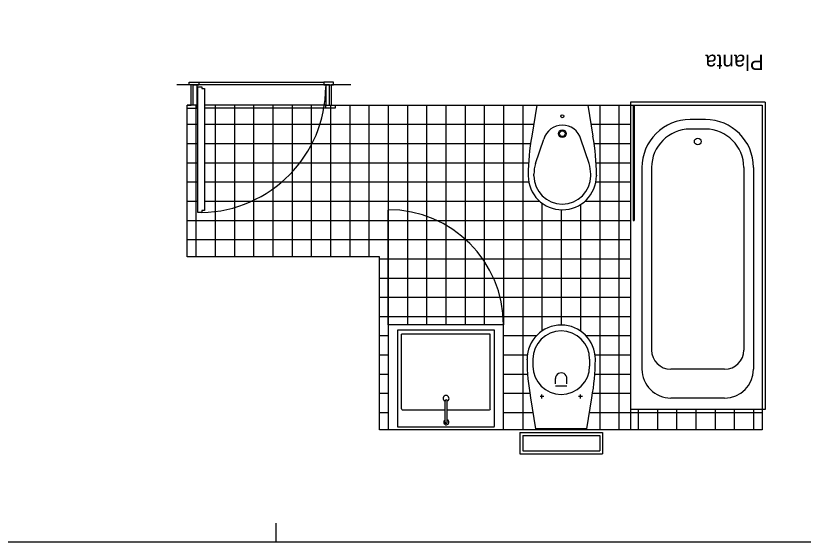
# Model space of a CAD drawing. Extents: x 1302 to 1313.6, y -284.7 to -278.8.
# Drawn here: x 1304.384 to 1308.48, y -284.712 to -281.971 of the extents above; entities that cross this region are included whole.
import ezdxf

# ---------------------------------------------------------------- set-up
doc = ezdxf.new("R2010")
doc.units = 0
for name, color, linetype in [('Level 1', 7, 'Continuous'), ('Level 10', 7, 'Continuous'), ('Level 11', 7, 'Continuous'), ('Level 13', 7, 'Continuous'), ('Level 2', 7, 'Continuous'), ('Level 36', 7, 'Continuous'), ('Level 4', 7, 'Continuous'), ('Level 60', 7, 'Continuous'), ('Level 62', 7, 'Continuous')]:
    doc.layers.add(name, color=color, linetype=linetype)

msp = doc.modelspace()

# ---------------------------------------------------------------- linework, layer by layer
at = {"layer": 'Level 1'}
for p, q in [((1305.2959, -282.3311), (1305.2209, -282.3311)), ((1305.2959, -282.4361), (1305.2959, -282.3311)), ((1306.1259, -282.3311), (1306.0259, -282.3311)), ((1306.0259, -282.4361), (1306.0259, -282.3311)), ((1305.2759, -283.2261), (1305.2759, -282.4361)), ((1305.2759, -282.4361), (1305.2959, -282.4361)), ((1306.0259, -282.4361), (1308.2659, -282.4361)), ((1308.2659, -282.4361), (1308.2659, -284.1261)), ((1306.2759, -283.2261), (1305.2759, -283.2261)), ((1306.2759, -284.1261), (1306.2759, -283.2261)), ((1308.2659, -284.1261), (1306.2759, -284.1261))]:
    msp.add_line(p, q, dxfattribs=at)
at = {"layer": 'Level 10'}
for p, q in [((1305.9859, -282.3311), (1305.3359, -282.3311)), ((1305.3209, -282.4361), (1305.3209, -283.2261)), ((1305.9959, -282.4361), (1305.3659, -282.4361)), ((1305.4209, -282.4361), (1305.4209, -283.2261)), ((1305.5209, -282.4361), (1305.5209, -283.2261)), ((1305.6209, -282.4361), (1305.6209, -283.2261)), ((1305.7209, -282.4361), (1305.7209, -283.2261)), ((1305.8209, -282.4361), (1305.8209, -283.2261)), ((1305.9209, -282.4361), (1305.9209, -283.2261)), ((1306.0209, -282.4361), (1306.0209, -283.2261)), ((1306.1209, -282.4361), (1306.1209, -283.2261)), ((1306.2209, -282.4361), (1306.2209, -283.2261)), ((1306.3209, -282.4361), (1306.3209, -283.5806)), ((1306.4209, -282.4361), (1306.4209, -283.5806)), ((1306.5209, -282.4361), (1306.5209, -283.5806)), ((1306.6209, -282.4361), (1306.6209, -283.5806)), ((1306.7209, -282.4361), (1306.7209, -283.5806)), ((1306.8209, -282.4361), (1306.8209, -283.5806)), ((1306.9209, -282.4361), (1306.9209, -283.5806)), ((1307.0209, -282.4361), (1307.0209, -284.1261)), ((1307.4209, -282.4361), (1307.4209, -284.1261)), ((1307.5209, -282.4361), (1307.5209, -284.1261)), ((1305.2759, -282.5361), (1305.3309, -282.5361)), ((1305.3659, -282.5361), (1307.0778, -282.5361)), ((1307.3753, -282.5361), (1307.5809, -282.5361)), ((1305.2759, -282.6361), (1305.3309, -282.6361)), ((1305.3659, -282.6361), (1307.0613, -282.6361)), ((1307.3919, -282.6361), (1307.5809, -282.6361)), ((1305.2759, -282.7361), (1305.3309, -282.7361)), ((1305.3659, -282.7361), (1307.0509, -282.7361)), ((1307.4022, -282.7361), (1307.5809, -282.7361)), ((1305.2759, -282.8361), (1305.3309, -282.8361)), ((1305.3659, -282.8361), (1307.0521, -282.8361)), ((1307.4011, -282.8361), (1307.5809, -282.8361)), ((1305.2759, -282.9361), (1305.3309, -282.9361)), ((1305.3659, -282.9361), (1307.1085, -282.9361)), ((1307.1209, -282.9462), (1307.1209, -283.6121)), ((1307.3209, -282.9539), (1307.3209, -283.6121)), ((1307.3447, -282.9361), (1307.5809, -282.9361)), ((1307.2209, -282.981), (1307.2209, -283.5812)), ((1305.2759, -283.0361), (1307.5809, -283.0361)), ((1305.2759, -283.1361), (1307.5809, -283.1361)), ((1306.2759, -283.2361), (1307.5809, -283.2361)), ((1306.2759, -283.3361), (1307.5809, -283.3361)), ((1306.2759, -283.4361), (1307.5809, -283.4361)), ((1306.2759, -283.5361), (1307.5809, -283.5361)), ((1306.2759, -283.6361), (1306.3211, -283.6361)), ((1306.9209, -283.6361), (1307.0926, -283.6361)), ((1307.3492, -283.6361), (1307.5809, -283.6361)), ((1306.2759, -283.7361), (1306.3211, -283.7361)), ((1306.9209, -283.7361), (1307.0449, -283.7361)), ((1307.397, -283.7361), (1307.5809, -283.7361)), ((1306.2759, -283.8361), (1306.3211, -283.8361)), ((1306.9209, -283.8361), (1307.046, -283.8361)), ((1307.3958, -283.8361), (1307.5809, -283.8361)), ((1306.2759, -283.9361), (1306.3211, -283.9361)), ((1306.9209, -283.9361), (1307.0582, -283.9361)), ((1307.3837, -283.9361), (1307.5809, -283.9361)), ((1307.6209, -284.0211), (1307.6209, -284.1245)), ((1307.7209, -284.0211), (1307.7209, -284.1245)), ((1307.8209, -284.0211), (1307.8209, -284.1245)), ((1307.9209, -284.0211), (1307.9209, -284.1245)), ((1308.0209, -284.0211), (1308.0209, -284.1245)), ((1308.1209, -284.0211), (1308.1209, -284.1245)), ((1308.2209, -284.0211), (1308.2209, -284.1245)), ((1306.2759, -284.0361), (1306.3211, -284.0361)), ((1306.9209, -284.0361), (1307.0746, -284.0361)), ((1307.3673, -284.0361), (1308.2659, -284.0361))]:
    msp.add_line(p, q, dxfattribs=at)
at = {"layer": 'Level 11'}
for p, q in [((1308.2809, -282.4211), (1307.5809, -282.4211)), ((1307.5809, -282.4211), (1307.5809, -284.0211)), ((1308.2809, -282.4211), (1308.2809, -284.0211)), ((1307.0942, -282.4361), (1307.0676, -282.5981)), ((1307.0942, -282.4361), (1307.3589, -282.4361)), ((1307.3589, -282.4361), (1307.3855, -282.5981)), ((1307.9709, -282.5111), (1307.8909, -282.5111)), ((1307.9709, -282.5611), (1307.8909, -282.5611)), ((1307.0867, -282.7406), (1307.1304, -282.6126)), ((1307.3664, -282.7406), (1307.3227, -282.6126)), ((1307.0791, -282.8036), (1307.0791, -282.7955)), ((1307.3741, -282.8036), (1307.3741, -282.7955)), ((1307.6409, -282.7611), (1307.6409, -283.8111)), ((1307.6909, -282.7611), (1307.6909, -283.7111)), ((1308.1709, -282.7611), (1308.1709, -283.7111)), ((1308.2209, -282.7611), (1308.2209, -283.8111)), ((1307.0491, -282.8002), (1307.0491, -282.8039)), ((1307.4041, -282.8002), (1307.4041, -282.8039)), ((1306.3688, -283.6079), (1306.3688, -284.1071)), ((1306.8732, -283.6079), (1306.3688, -283.6079)), ((1306.8732, -284.1071), (1306.8732, -283.6079)), ((1306.3899, -284.0175), (1306.3899, -283.629)), ((1306.8521, -283.629), (1306.3899, -283.629)), ((1306.8521, -284.0175), (1306.8521, -283.629)), ((1307.0434, -283.7621), (1307.0434, -283.7584)), ((1307.0734, -283.7587), (1307.0734, -283.7948)), ((1307.3684, -283.7587), (1307.3684, -283.7948)), ((1307.3984, -283.7621), (1307.3984, -283.7584)), ((1308.0709, -283.8111), (1307.7909, -283.8111)), ((1307.1909, -283.8867), (1307.1909, -283.8595)), ((1307.2509, -283.8867), (1307.2509, -283.8596)), ((1307.2509, -283.899), (1307.1909, -283.899)), ((1307.1209, -283.9631), (1307.1209, -283.9431)), ((1307.3209, -283.9631), (1307.3209, -283.9431)), ((1306.6171, -284.0863), (1306.6171, -283.9768)), ((1306.6284, -284.0863), (1306.6284, -283.9768)), ((1307.0886, -284.1212), (1307.062, -283.9592)), ((1307.1309, -283.9531), (1307.1109, -283.9531)), ((1307.3309, -283.9531), (1307.3109, -283.9531)), ((1307.3533, -284.1212), (1307.3799, -283.9592)), ((1308.0709, -283.9611), (1307.7909, -283.9611)), ((1306.3943, -284.0219), (1306.6171, -284.0219)), ((1306.6284, -284.0219), (1306.8478, -284.0219)), ((1308.2809, -284.0211), (1307.5809, -284.0211)), ((1306.3732, -284.1115), (1306.8688, -284.1115)), ((1307.0059, -284.1412), (1307.0059, -284.2512)), ((1307.0059, -284.1412), (1307.4359, -284.1412)), ((1307.3533, -284.1212), (1307.0886, -284.1212)), ((1307.4359, -284.1412), (1307.4359, -284.2512)), ((1307.0209, -284.1562), (1307.4209, -284.1562)), ((1307.0209, -284.1562), (1307.0209, -284.2362)), ((1307.4209, -284.1562), (1307.4209, -284.2362)), ((1307.0059, -284.2512), (1307.4359, -284.2512)), ((1307.0209, -284.2362), (1307.4209, -284.2362))]:
    msp.add_line(p, q, dxfattribs=at)
for centre, radius in [((1307.2266, -282.4941), 0.00766), ((1307.2266, -282.5849), 0.02), ((1307.2266, -282.5849), 0.0146), ((1307.9309, -282.6255), 0.0173)]:
    msp.add_circle(centre, radius, dxfattribs=at)
for centre, radius, start, end in [((1307.8909, -282.7611), 0.25, 89.9999, 180), ((1307.9709, -282.7611), 0.25, 0.0001, 90.0001), ((1307.2266, -282.6401), 0.1, 15.9317, 164.1953), ((1307.8909, -282.7611), 0.2, 90, 180), ((1307.9709, -282.7611), 0.2, 360, 90), ((1307.2791, -282.7955), 0.2, 164.0693, 180.0006), ((1307.1741, -282.7955), 0.2, 0.0017, 15.9319), ((1307.2266, -282.8036), 0.1775, 180.0002, 359.9999), ((1307.2266, -282.8036), 0.1475, 180.0002, 359.9999), ((1307.2209, -283.7587), 0.1775, 0.0002, 179.9999), ((1307.2209, -283.7587), 0.1475, 0.0002, 179.9999), ((1307.7909, -283.7111), 0.1, 180.0001, 269.9999), ((1308.0709, -283.7111), 0.1, 270, 0), ((1307.2209, -283.7948), 0.1475, 180.0002, 359.9999), ((1307.7909, -283.8111), 0.15, 179.9998, 270.0001), ((1308.0709, -283.8111), 0.15, 270, 0), ((1307.2209, -283.8597), 0.03, 359.9995, 180.0013), ((1306.6224, -283.9624), 0.015, 293.6307, 249.2833), ((1306.6227, -283.9762), 0.00566, 354.0176, 185.9962), ((1306.3943, -284.0175), 0.00438, 180, 270), ((1306.8478, -284.0175), 0.00438, 270, 0), ((1306.3732, -284.1071), 0.00438, 180, 270), ((1306.6232, -284.0869), 0.0135, 116.7199, 67.3909), ((1306.6227, -284.0869), 0.00566, 174.0038, 5.9824), ((1306.8688, -284.1071), 0.00438, 270, 0)]:
    msp.add_arc(centre, radius, start, end, dxfattribs=at)
for centre, major_axis, ratio, start_param, end_param in [((1308.4491, -282.8002), (-1.4, 0), 0.88995, 6.120269, 6.283187), ((1306.0041, -282.8002), (1.4, 0), 0.88995, 6.283183, 6.446102), ((1308.4434, -283.7621), (-1.4, 0), 0.867931, 6.283184, 6.446103), ((1305.9984, -283.7621), (1.4, 0), 0.867931, 6.120269, 6.283188)]:
    msp.add_ellipse(centre, major_axis=major_axis, ratio=ratio, start_param=start_param, end_param=end_param, dxfattribs=at)
at = {"layer": 'Level 13'}
for p, q in [((1305.2859, -282.3161), (1305.3359, -282.3161)), ((1305.2859, -282.3311), (1305.2859, -282.3161)), ((1305.3359, -282.3311), (1305.2859, -282.3311)), ((1305.3059, -282.4361), (1305.3059, -282.3311)), ((1305.3059, -282.3311), (1305.3359, -282.3311)), ((1305.3259, -282.3311), (1305.3259, -282.4361)), ((1305.3309, -282.9954), (1305.3309, -282.3404)), ((1305.3309, -282.3404), (1305.3509, -282.3404)), ((1305.3359, -282.3161), (1305.3359, -282.3311)), ((1305.3509, -282.3404), (1305.3509, -282.3504)), ((1306.0359, -282.3161), (1305.9859, -282.3161)), ((1305.9859, -282.3161), (1305.9859, -282.3311)), ((1306.0159, -282.3311), (1305.9859, -282.3311)), ((1305.9859, -282.3311), (1306.0359, -282.3311)), ((1305.9959, -282.3311), (1305.9959, -282.4361)), ((1306.0159, -282.4361), (1306.0159, -282.3311)), ((1306.0359, -282.3311), (1306.0359, -282.3161)), ((1305.3509, -282.3504), (1305.3659, -282.3504)), ((1305.3659, -282.3504), (1305.3659, -282.9854)), ((1305.3259, -282.4361), (1305.2759, -282.4361)), ((1305.2759, -282.4511), (1305.3259, -282.4511)), ((1305.3259, -282.4361), (1305.3059, -282.4361)), ((1305.3259, -282.4511), (1305.3259, -282.4361)), ((1305.9959, -282.4511), (1305.9959, -282.4361)), ((1305.9959, -282.4361), (1306.0159, -282.4361)), ((1305.9959, -282.4361), (1306.0459, -282.4361)), ((1306.0459, -282.4511), (1305.9959, -282.4511)), ((1306.0459, -282.4361), (1306.0459, -282.4511)), ((1305.3509, -282.9954), (1305.3309, -282.9954)), ((1305.3509, -282.9854), (1305.3509, -282.9951)), ((1305.3659, -282.9854), (1305.3509, -282.9854))]:
    msp.add_line(p, q, dxfattribs=at)
at = {"layer": 'Level 2'}
for p, q in [((1306.9209, -283.5806), (1306.3211, -283.5806)), ((1306.3211, -283.5806), (1306.3211, -284.1261)), ((1306.9209, -284.1261), (1306.9209, -283.5806)), ((1307.5809, -284.0211), (1307.5809, -284.1261))]:
    msp.add_line(p, q, dxfattribs=at)
at = {"layer": 'Level 36'}
for p, q in [((1307.5953, -282.4361), (1307.5953, -283.0361)), ((1307.6003, -282.4361), (1307.6003, -283.0361)), ((1307.5953, -283.0361), (1307.6003, -283.0361))]:
    msp.add_line(p, q, dxfattribs=at)
at = {"layer": 'Level 4'}
for p, q in [((1305.3359, -282.3161), (1305.9859, -282.3161)), ((1305.9959, -282.4511), (1305.3659, -282.4511)), ((1306.3209, -283.5806), (1306.3209, -282.9838))]:
    msp.add_line(p, q, dxfattribs=at)
msp.add_arc((1306.3209, -283.5806), 0.6, 0, 90, dxfattribs=at)
msp.add_ellipse((1305.3373, -282.3404), major_axis=(-0.6586, 0), ratio=0.994279, start_param=1.591512, end_param=3.141593, dxfattribs=at)
at = {"layer": 'Level 62'}
msp.add_line((1305.7367, -284.6118), (1305.7367, -284.7118), dxfattribs=at)
msp.add_lwpolyline([(1313.6363, -278.7718), (1313.6363, -284.7118), (1302.0367, -284.7118), (1302.0367, -278.7718)], close=True, dxfattribs=at)

# ---------------------------------------------------------------- texts
at = {"layer": 'Level 60'}
msp.add_text('Planta', height=0.08, rotation=180, dxfattribs=at).set_placement((1308.2734, -282.1734))

doc.saveas('drawing.dxf')
